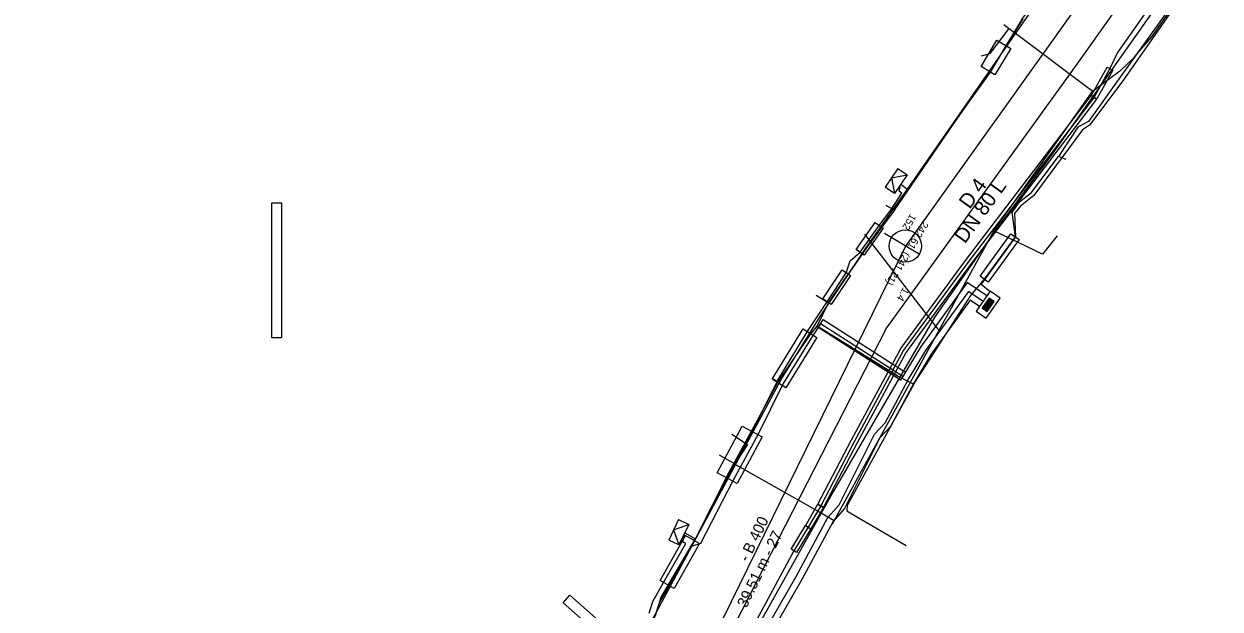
# Model space of a CAD drawing. Extents: x -600636 to -600148, y -1203980 to -1203569.
# Drawn here: x -600425.2 to -600351.2, y -1203776.3 to -1203740.1 of the extents above; entities that cross this region are included whole.
import ezdxf

# ---------------------------------------------------------------- set-up
doc = ezdxf.new("R2010")
doc.units = 0
for name, color, linetype in [('Cetin zam průběh', 7, 'Continuous'), ('EON objekty', 7, 'Continuous'), ('EON podzemní NN', 7, 'Continuous'), ('EON podzemní VN', 7, 'Continuous'), ('GasNet NTL', 7, 'Continuous'), ('Implicitní', 7, 'Continuous'), ('VaK Břeclav_kanalizace', 7, 'Continuous'), ('Vak Břeclav_vodovod', 7, 'Continuous'), ('Vrstva 9', 7, 'Continuous')]:
    doc.layers.add(name, color=color, linetype=linetype)

# ---------------------------------------------------------------- blocks, each defined once
blk = doc.blocks.new('NN630')
at = {"layer": 'Vrstva 9'}
for points in [[(-0.003, -0.7), (-0.703, 0)], [(-0.703, -0.7), (-0.703, 0), (0.697, 0), (0.697, -0.7)], [(-0.703, -0.7), (0.697, -0.7)], [(-0.003, -0.7), (0.697, 0)]]:
    blk.add_lwpolyline(points, dxfattribs=at)
blk = doc.blocks.new('NN620')
at = {"layer": 'EON objekty'}
for points in [[(0.752, 0.004), (-0.748, 0.004)], [(-0.748, 0.004), (-0.748, -0.746)], [(0.752, -0.746), (0.752, 0.004)], [(0.368, -0.18), (-0.376, -0.18)], [(-0.376, -0.18), (-0.376, -0.558)], [(-0.376, -0.558), (0.368, -0.558)], [(0.321, -0.227), (-0.329, -0.227)], [(-0.329, -0.227), (-0.329, -0.51)], [(-0.329, -0.51), (0.321, -0.51)], [(0.274, -0.274), (-0.281, -0.274)], [(-0.281, -0.274), (-0.281, -0.463)], [(-0.281, -0.463), (0.274, -0.463)], [(0.227, -0.321), (-0.234, -0.321)], [(-0.234, -0.321), (-0.234, -0.416)], [(-0.234, -0.416), (0.227, -0.416)], [(-0.193, -0.369), (0.185, -0.369)], [(0.227, -0.416), (0.227, -0.321)], [(0.274, -0.463), (0.274, -0.274)], [(0.321, -0.51), (0.321, -0.227)], [(0.368, -0.558), (0.368, -0.18)], [(-0.748, -0.746), (0.752, -0.746)]]:
    blk.add_lwpolyline(points, dxfattribs=at)
blk = doc.blocks.new('MoSymbol 2')
at = {"layer": 'Implicitní'}
blk.add_line((0, 0.0005), (0, -0.00075), dxfattribs=at)
blk.add_circle((0, 0), 0.0005, dxfattribs=at)

msp = doc.modelspace()

# ---------------------------------------------------------------- linework, layer by layer
at = {"layer": 'Cetin zam průběh'}
for points in [[(-600448.32, -1203764.77), (-600445.41, -1203766.9), (-600434.97, -1203774.92), (-600422.32, -1203783.12), (-600413.93, -1203789.04), (-600405.18, -1203794.93), (-600400.25, -1203797.98), (-600398.96, -1203798.36), (-600397.12, -1203797.36), (-600388.96, -1203781.95), (-600378.33, -1203762.13), (-600375.93, -1203758.23), (-600373.1, -1203754.01), (-600370.24, -1203749.96), (-600363.35, -1203740.04), (-600357.38, -1203731.69), (-600349.33, -1203720.15), (-600345.8, -1203715.19), (-600340.07, -1203706.96), (-600329.02, -1203689.27)], [(-600349.98, -1203733.11), (-600352.35, -1203736.35), (-600353.65, -1203738.25), (-600357.31, -1203743.38), (-600359.31, -1203746.17), (-600359.98, -1203746.53), (-600361.18, -1203748.34)], [(-600371.33, -1203751.67), (-600367.69, -1203746.37), (-600365.25, -1203742.89), (-600363.56, -1203740.1), (-600363.39, -1203739.78), (-600362.14, -1203738.07)], [(-600365.25, -1203742.89), (-600363.56, -1203740.1)], [(-600370.13, -1203762.42), (-600366.6, -1203756.94), (-600365.75, -1203755.93), (-600363.84, -1203753.31), (-600364.05, -1203751.8), (-600363.56, -1203751.12), (-600362.86, -1203750.58), (-600361.18, -1203748.34)], [(-600360.7, -1203748.52), (-600361.18, -1203748.34)], [(-600371.33, -1203751.67), (-600371.96, -1203752.5), (-600372.95, -1203753.85), (-600374.23, -1203755.69), (-600375.4, -1203757.39)], [(-600371.85, -1203751.35), (-600371.33, -1203751.67)], [(-600372.95, -1203753.85), (-600371.96, -1203752.5)], [(-600365.75, -1203755.93), (-600363.84, -1203753.31)], [(-600375.4, -1203757.39), (-600374.23, -1203755.69)], [(-600376.17, -1203756.91), (-600375.4, -1203757.39)], [(-600376.1, -1203758.83), (-600375.4, -1203757.39)], [(-600378.52, -1203762.28), (-600376.55, -1203759.37), (-600376.1, -1203758.83)], [(-600378.52, -1203762.28), (-600376.55, -1203759.37)], [(-600371.11, -1203761.93), (-600376.1, -1203758.83)], [(-600376.1, -1203758.83), (-600371.11, -1203761.93), (-600370.13, -1203762.42)], [(-600383.64, -1203771.99), (-600381.53, -1203767.83), (-600380.04, -1203765.1), (-600378.52, -1203762.28)], [(-600378.9, -1203762.06), (-600378.52, -1203762.28)], [(-600370.13, -1203762.42), (-600374.25, -1203769.92), (-600374.28, -1203770.27), (-600373.61, -1203770.66), (-600370.61, -1203772.41)], [(-600381.53, -1203767.83), (-600380.04, -1203765.1)], [(-600384.3, -1203771.63), (-600383.64, -1203771.99)], [(-600396.69, -1203794.26), (-600395.96, -1203792.99), (-600395.05, -1203791.52), (-600394.27, -1203790.24), (-600392.18, -1203786.77), (-600391.09, -1203785.14), (-600390.52, -1203784.22), (-600388.33, -1203780.56), (-600387.91, -1203779.78), (-600386.07, -1203776.57), (-600385.86, -1203775.96), (-600385.78, -1203775.65), (-600383.64, -1203771.99)], [(-600385.78, -1203775.65), (-600383.64, -1203771.99)]]:
    msp.add_lwpolyline(points, dxfattribs=at)
at = {"layer": 'EON podzemní NN'}
for points in [[(-600353.56, -1203738.45), (-600357.2, -1203743.67), (-600359.26, -1203746.4), (-600359.69, -1203746.7), (-600360.991, -1203748.45), (-600361.23, -1203748.771), (-600362.71, -1203750.75), (-600363.52, -1203751.41), (-600363.89, -1203751.87), (-600363.84, -1203753.31), (-600365.958, -1203756.243), (-600365.403, -1203756.689)], [(-600386.496, -1203776.592), (-600386.286, -1203775.861), (-600385.614, -1203774.691), (-600384.24, -1203772.273), (-600384.41, -1203772.193), (-600384.356, -1203771.737), (-600383.679, -1203772.095), (-600381.673, -1203768.224), (-600380.134, -1203765.366), (-600378.549, -1203762.184), (-600376.72, -1203759.19), (-600375.5, -1203757.33), (-600374.31, -1203755.54), (-600374.06, -1203754.79), (-600373.45, -1203754.27), (-600372.28, -1203752.61), (-600371.56, -1203751.66), (-600370.878, -1203750.607), (-600371.042, -1203750.484), (-600370.94, -1203750.06), (-600370.5, -1203750.391), (-600368.596, -1203747.604), (-600365.393, -1203743.13), (-600364.409, -1203741.504), (-600363.365, -1203739.833)], [(-600365.605, -1203756.969), (-600366.826, -1203756.134), (-600369.718, -1203760.128), (-600370.812, -1203761.945), (-600375.9, -1203758.698), (-600376.384, -1203759.407), (-600378.208, -1203762.393), (-600379.783, -1203765.558), (-600381.32, -1203768.411), (-600383.328, -1203772.286), (-600383.91, -1203772.46), (-600385.267, -1203774.889), (-600385.915, -1203776.018), (-600386.125, -1203776.749), (-600387.914, -1203779.875), (-600388.206, -1203780.448), (-600390.566, -1203784.297), (-600391.528, -1203783.719)], [(-600382.7, -1203783.539), (-600377.4, -1203774.316), (-600375.451, -1203770.681), (-600374.755, -1203769.885), (-600372.562, -1203765.52), (-600371.908, -1203764.815), (-600370.453, -1203762.124), (-600369.384, -1203760.349), (-600366.73, -1203756.684), (-600365.831, -1203757.299)], [(-600366.057, -1203757.629), (-600366.635, -1203757.234), (-600369.05, -1203760.57), (-600370.11, -1203762.33), (-600371.58, -1203765.05), (-600372.23, -1203765.75), (-600374.42, -1203770.11), (-600375.12, -1203770.91), (-600377.05, -1203774.51), (-600382.44, -1203783.89), (-600383.8, -1203784.2), (-600384.6, -1203785.48), (-600384.21, -1203786.64), (-600384.56, -1203787.45)]]:
    msp.add_lwpolyline(points, dxfattribs=at)
for points in [[(-600364.981, -1203741.148), (-600364.126, -1203741.666), (-600365.106, -1203743.289), (-600365.963, -1203742.771)], [(-600409.846, -1203751.208), (-600409.246, -1203751.208), (-600409.246, -1203759.555), (-600409.846, -1203759.555)], [(-600372.527, -1203752.433), (-600372.026, -1203752.784), (-600373.192, -1203754.447), (-600373.695, -1203754.094)], [(-600364.127, -1203753.116), (-600363.619, -1203753.485), (-600365.525, -1203756.108), (-600366.029, -1203755.744)], [(-600374.56, -1203755.361), (-600374.053, -1203755.697), (-600375.24, -1203757.489), (-600375.75, -1203757.149)], [(-600370.65, -1203761.68), (-600370.962, -1203762.17), (-600376.047, -1203758.92), (-600375.737, -1203758.433)], [(-600376.972, -1203759.008), (-600376.121, -1203759.534), (-600378.048, -1203762.643), (-600378.895, -1203762.118)], [(-600380.747, -1203765.027), (-600379.515, -1203765.69), (-600381.062, -1203768.565), (-600382.295, -1203767.901)], [(-600384.26, -1203771.788), (-600383.387, -1203772.283), (-600384.959, -1203775.056), (-600385.829, -1203774.564)], [(-600391.835, -1203775.947), (-600391.413, -1203775.471), (-600388.235, -1203778.285), (-600388.656, -1203778.76)]]:
    msp.add_lwpolyline(points, close=True, dxfattribs=at)
at = {"layer": 'EON podzemní VN'}
for points in [[(-600366.95, -1203635.593), (-600366.181, -1203636.795), (-600358.381, -1203643.411), (-600344.954, -1203653.759), (-600330.827, -1203664.425), (-600321.645, -1203670.963), (-600317.713, -1203673.458), (-600315.791, -1203674.896), (-600315.293, -1203675.777), (-600315.944, -1203682.246), (-600316.226, -1203683.581), (-600322.501, -1203693.042), (-600331.079, -1203704.985), (-600348.911, -1203730.288), (-600354.208, -1203737.743), (-600361.516, -1203748.136), (-600365.138, -1203753.003), (-600368.824, -1203758.254), (-600375.091, -1203769.039), (-600381.398, -1203780.278), (-600382.49, -1203782.6), (-600383.25, -1203783.59)], [(-600351.367, -1203733.129), (-600357.517, -1203741.909), (-600357.997, -1203742.909), (-600358.977, -1203744.679), (-600366.777, -1203754.899), (-600370.767, -1203760.329), (-600373.807, -1203765.959), (-600375.887, -1203769.949), (-600376.667, -1203771.279), (-600377.557, -1203772.739), (-600383.047, -1203782.909), (-600383.307, -1203783.299)]]:
    msp.add_lwpolyline(points, dxfattribs=at)
for points in [[(-600359.152, -1203744.582), (-600358.172, -1203742.812), (-600357.822, -1203743.006), (-600358.802, -1203744.776)], [(-600359.136, -1203744.558), (-600358.818, -1203744.8), (-600366.617, -1203755.019), (-600370.597, -1203760.436), (-600373.63, -1203766.053), (-600375.709, -1203770.041), (-600376.064, -1203769.856), (-600373.983, -1203765.865), (-600370.936, -1203760.222), (-600366.937, -1203754.779)], [(-600376.059, -1203769.848), (-600375.714, -1203770.05), (-600376.494, -1203771.38), (-600376.839, -1203771.178)], [(-600376.837, -1203771.175), (-600376.496, -1203771.383), (-600377.386, -1203772.843), (-600377.727, -1203772.635)]]:
    msp.add_lwpolyline(points, close=True, dxfattribs=at)
at = {"layer": 'GasNet NTL'}
for points in [[(-600321.69, -1203692.03), (-600330.58, -1203705.33), (-600337.06, -1203714.26), (-600337.47, -1203714.88), (-600341.61, -1203721.03), (-600343.93, -1203724.48), (-600344.29, -1203725.01), (-600352.8, -1203737.19), (-600355.42, -1203740.94), (-600356.36, -1203742.04), (-600356.56, -1203742.28), (-600357.37, -1203743.06), (-600358.82, -1203744.14), (-600359.04, -1203744.31), (-600359.16, -1203744.4), (-600365.08, -1203752.77), (-600365.18, -1203752.95), (-600368.57, -1203759.1), (-600375.05, -1203770.85), (-600375.18, -1203771.08)], [(-600365.94, -1203742.11), (-600365.4, -1203741.98), (-600364.23, -1203740.42)], [(-600364.55, -1203740.18), (-600364.23, -1203740.42)], [(-600364.23, -1203740.42), (-600363.75, -1203740.78), (-600359.35, -1203744.08), (-600359.04, -1203744.31)], [(-600373.19, -1203753.14), (-600368.57, -1203759.1)], [(-600361.26, -1203753.26), (-600362.16, -1203754.39), (-600365.18, -1203752.95)], [(-600381.38, -1203765.52), (-600380.42, -1203766.15), (-600381.2, -1203767.36)], [(-600382.18, -1203766.8), (-600381.2, -1203767.36)], [(-600381.2, -1203767.36), (-600381.01, -1203767.47), (-600375.79, -1203770.42), (-600375.05, -1203770.85)]]:
    msp.add_lwpolyline(points, dxfattribs=at)
at = {"layer": 'VaK Břeclav_kanalizace'}
for p, q in [((-600337.248, -1203707.145), (-600370.65, -1203753.88)), ((-600370.65, -1203753.88), (-600388.037, -1203789.358))]:
    msp.add_line(p, q, dxfattribs=at)
at = {"layer": 'Vak Břeclav_vodovod'}
msp.add_lwpolyline([(-600330.382, -1203700.926), (-600340.064, -1203714.494), (-600360.044, -1203742.638), (-600371.815, -1203758.94), (-600385.686, -1203786.009), (-600395.742, -1203804.116)], dxfattribs=at)

# ---------------------------------------------------------------- block references
at = {"layer": 'EON podzemní NN'}
for name, p, rotation in [('NN630', (-600370.94, -1203750.06), -124.38137510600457), ('NN620', (-600365.83, -1203757.3), 55.011149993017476), ('NN630', (-600384.36, -1203771.74), -115.42863054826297)]:
    msp.add_blockref(name, p, dxfattribs=dict(at, rotation=rotation))
at = {"layer": 'VaK Břeclav_kanalizace', "xscale": 1999.7500312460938, "yscale": 1999.7500312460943, "rotation": -120.83113433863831}
msp.add_blockref('MoSymbol 2', (-600370.65, -1203753.88), dxfattribs=at)

# ---------------------------------------------------------------- texts
at = {"layer": 'VaK Břeclav_kanalizace'}
for s, height, rotation, p in [('152', 0.4549, 239.16887, (-600370.334, -1203751.85)), ('242,61  (241,21)', 0.45494, 239.16887, (-600369.586, -1203752.31)), ('1.4', 0.4549, 239.16887, (-600370.774, -1203756.4)), ('- B 400', 0.6824, 63.89153, (-600380.387, -1203773.467)), ('39.51 m - 27', 0.68241, 63.89153, (-600380.49, -1203776.308))]:
    msp.add_text(s, height=height, rotation=rotation, dxfattribs=at).set_placement(p)
at = {"layer": 'Vak Břeclav_vodovod'}
for s, p in [('D 4', (-600366.674, -1203751.644)), ('DN 80 L', (-600366.964, -1203753.776))]:
    msp.add_text(s, height=0.9099, rotation=54.16851, dxfattribs=at).set_placement(p)

doc.saveas('drawing.dxf')
